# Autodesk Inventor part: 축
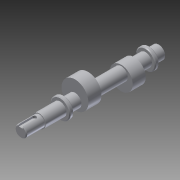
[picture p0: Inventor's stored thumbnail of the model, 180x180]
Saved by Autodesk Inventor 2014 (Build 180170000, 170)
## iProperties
Created: 2014-12
Part Number: 축
Material: 알루미늄 6061
Document SubType Name: Modeling
Designer: Owner
Mass: 170.354 g
Surface Area: 153.402 cm^2
Volume: 62.8614 cm^3
Density: 2.71 g/cm^3
Appearance: 알루미늄 - 평지
Author: Owner
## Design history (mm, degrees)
sketch "스케치3"
  geometry: L1 (-90, 0)-(90, 0); L2 (-90, 0)-(-90, 7.5); L3 (-90, 7.5)-(-66, 7.5); L4 (-66, 7.5)-(-66, 8.5); L5 (-66, 8.5)-(-39, 8.5); L6 (-39, 8.5)-(-39, 13); L7 (-39, 13)-(-34, 13); L8 (-34, 13)-(-34, 8.5); L9 (-34, 8.5)-(72, 8.5); L10 (72, 8.5)-(72, 13); L11 (72, 13)-(77, 13); L12 (77, 13)-(77, 8.5); L13 (77, 8.5)-(90, 8.5); L14 (90, 8.5)-(90, 0); 2 further points
  constraints: 28 end point, 11 parallel, 2 perpendicular, 1 coincident, 1 horizontal, 1 horizontal alignment, 1 midpoint, 1 vertical alignment
  dimensions: "d16" = 180 distance of L1.start L1.end; "d17" = 15 diameter of L3 L1; "d18" = 17 diameter of L5 L1; "d19" = 27 distance of L5.end L4.end; "d20" = 24 distance of L2.end L3.end; "d21" = 26 diameter of L7 L1; "d22" = 5 distance of L6.end L7.end; "d23" = 17 diameter of L13.end L1; "d24" = 26 diameter of L11 L1; "d25" = 13 distance of L12.end L13.end; "d26" = 5 distance of L10.end L11.end
revolve "회전1" sketch "스케치3" stored, may be unused: angle "d27" = 90 deg
node "작업 평면1"
sketch "스케치4"
  geometry: L1 (7.5, -12)-(-7.5, -12) reference; L2 (7.5, -12)-(7.5, 12) reference; L3 (-7.5, -12)-(-7.5, 12) reference; L4 (0, -29.5)-(0, 5.5); L5 (2.5, -12)-(2.5, 5.5); L6 (-2.5, 5.5)-(-2.5, -12); L7 (-2.5, -12)-(2.5, -12); A1 r 2.5 centre (0, 5.5) between (2.5, 5.5) and (-2.5, 5.5); 4 further points
  constraints: 10 end point, 3 midpoint, 2 point on circle, 2 tangent, 2 vertical alignment, 1 centre point, 1 coincident, 1 horizontal alignment, 1 parallel, 1 perpendicular, 1 point on line
  dimensions: "d28" = 20 dimension on A1 L1; "d29" = 5 distance between parallel lines of L5 L6
extrude "돌출1" cut sketch "스케치4" distance "d30" = 3; taper "d31" = 0 deg
node "작업 평면2"
sketch "스케치5"
  geometry: C1 r 17.5 at (0, 6); 1 further point
  constraints: 1 centre point, 1 vertical alignment
  dimensions: "d33" = 35 diameter of C1; "d34" = 6 distance of C1.centre point (0, 0)
extrude "돌출2" join sketch "스케치5" distance "d35" = 17; taper "d36" = 0 deg
node "작업 평면3"
sketch "스케치6"
  geometry: C1 r 15 at (0, -5); 1 further point
  constraints: 1 centre point, 1 vertical alignment
  dimensions: "d38" = 30 diameter of C1; "d39" = 5 distance of C1.centre point (0, 0)
extrude "돌출3" join sketch "스케치6" distance "d40" = 17; taper "d41" = 0 deg
chamfer "모따기1" distance "d42" = 1; stored, may be unused: second distance "d43" = 2, angle "d44" = 45 deg
chamfer "모따기2" distance "d45" = 1; stored, may be unused: second distance "d46" = 2, angle "d47" = 45 deg
node "솔리드1"
other parameters: "d32" = -19.5, "d37" = 40.5
